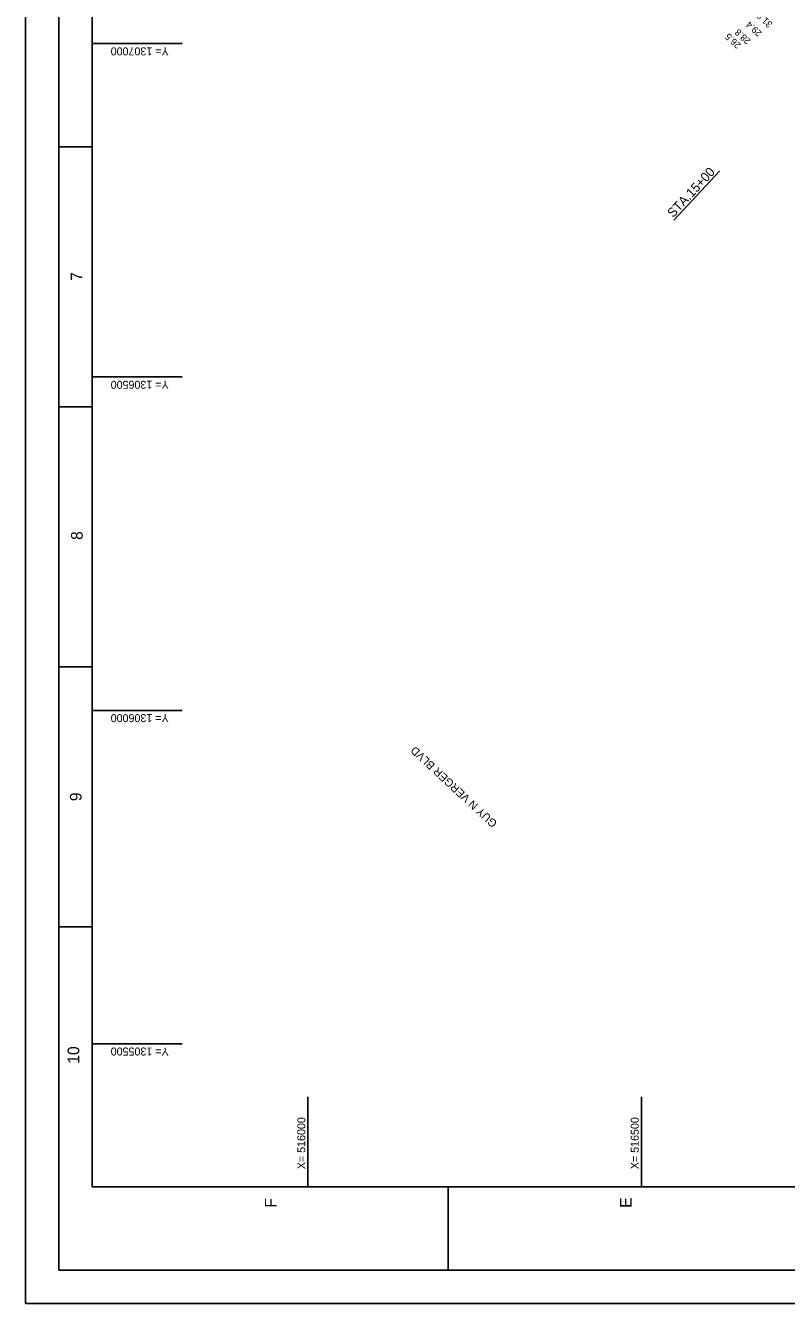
# Model space of a CAD drawing. Extents: x 515576 to 518976, y 1305110 to 1309511.
# Drawn here: x 515576 to 516718, y 1305110 to 1307027 of the extents above; entities that cross this region are included whole.
import ezdxf

# ---------------------------------------------------------------- set-up
doc = ezdxf.new("R2010")
doc.units = 0
for name, color, linetype in [('G-ANNO-NPLT', 7, 'Continuous'), ('G-ANNO-TTLB', 7, 'Continuous'), ('V-ALGN-TEXT', 7, 'Continuous'), ('V-ROAD-IDEN', 7, 'Continuous'), ('V-TOPO-COOR-STAT', 7, 'Continuous'), ('V-TOPO-SOUN', 7, 'Continuous')]:
    doc.layers.add(name, color=color, linetype=linetype)

msp = doc.modelspace()

# ---------------------------------------------------------------- linework, layer by layer
at = {"layer": 'G-ANNO-NPLT'}
msp.add_lwpolyline([(515576.5, 1305110.5), (515576.5, 1309510.4), (518976.4, 1309510.4), (518976.4, 1305110.5)], close=True, dxfattribs=at)
msp.add_lwpolyline([(515626.5, 1305110.5), (515576.5, 1305110.5), (515576.5, 1305160.5)], dxfattribs=at)
at = {"layer": 'G-ANNO-TTLB'}
for p, q in [((515626.5, 1306845.4), (515676.5, 1306845.4)), ((515626.5, 1306455.4), (515676.5, 1306455.4)), ((515626.5, 1306065.4), (515676.5, 1306065.4)), ((515626.5, 1306065.4), (515676.5, 1306065.4)), ((515626.5, 1305675.5), (515676.5, 1305675.5)), ((516210, 1305160.5), (516210, 1305285.5))]:
    msp.add_line(p, q, dxfattribs=at)
for points in [[(518926.4, 1305160.5), (518926.4, 1309460.4), (515626.5, 1309460.4), (515626.5, 1305160.5)], [(515676.5, 1309410.4), (515676.5, 1305285.5), (518876.4, 1305285.5), (518876.4, 1309410.4)]]:
    msp.add_lwpolyline(points, close=True, dxfattribs=at)
at = {"layer": 'V-ALGN-TEXT'}
msp.add_line((516617.1, 1306808.5), (516548.9, 1306735.4), dxfattribs=at)
at = {"layer": 'V-TOPO-COOR-STAT'}
for p, q in [((515811.5, 1307000), (515676.5, 1307000)), ((515811.5, 1306500), (515676.5, 1306500)), ((515811.5, 1306000), (515676.5, 1306000)), ((515811.5, 1305500), (515676.5, 1305500)), ((516000, 1305285.5), (516000, 1305420.5)), ((516500, 1305285.5), (516500, 1305420.5))]:
    msp.add_line(p, q, dxfattribs=at)

# ---------------------------------------------------------------- texts
at = {"layer": 'G-ANNO-TTLB'}
for s, p in [('7', (515661.5, 1306644.3)), ('8', (515662.2, 1306255.6)), ('9', (515660.5, 1305863.8)), ('10', (515657, 1305470)), ('F', (515952.8, 1305254)), ('E', (516485.5, 1305253.9))]:
    msp.add_text(s, height=17.5, rotation=90, dxfattribs=at).set_placement(p)
at = {"layer": 'V-ALGN-TEXT'}
msp.add_text('STA.15+00', height=13.92, rotation=46.9628, dxfattribs=at).set_placement((516547.5, 1306738))
at = {"layer": 'V-ROAD-IDEN'}
msp.add_text('GUY N VERGER BLVD', height=12, rotation=137.0497, dxfattribs=at).set_placement((516284.7, 1305831.7))
at = {"layer": 'V-TOPO-COOR-STAT'}
for s, rotation, p in [('Y= 1307000', 180, (515791.1, 1306994.3)), ('Y= 1306500', 180, (515791.1, 1306494.3)), ('Y= 1306000', 180, (515791.1, 1305994.3)), ('Y= 1305500', 180, (515791.1, 1305494.3)), ('X= 516000', 90, (515996, 1305311.8)), ('X= 516500', 90, (516496, 1305311.8))]:
    msp.add_text(s, height=12, rotation=rotation, dxfattribs=at).set_placement(p)
at = {"layer": 'V-TOPO-SOUN'}
for s, p in [('31.0 ', (516697.3, 1307030.1)), ('28.8 ', (516664.8, 1307005)), ('29.4 ', (516681.6, 1307016.7)), ('26.5 ', (516650.2, 1306998.6))]:
    msp.add_text(s, height=10, rotation=136.9626, dxfattribs=at).set_placement(p)

doc.saveas('drawing.dxf')
